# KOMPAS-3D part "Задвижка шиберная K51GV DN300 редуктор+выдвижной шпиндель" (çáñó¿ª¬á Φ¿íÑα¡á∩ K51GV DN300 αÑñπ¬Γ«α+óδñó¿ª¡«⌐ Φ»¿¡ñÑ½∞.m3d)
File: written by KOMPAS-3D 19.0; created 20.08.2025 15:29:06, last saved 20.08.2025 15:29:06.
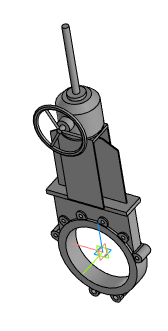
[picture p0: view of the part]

Document properties: Полное имя файла: Задвижка шиберная K51GV DN300 редуктор+выдвижной шпиндель.a3d

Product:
- Part/product: Задвижка шиберная K51GV DN300 редуктор+выдвижной шпиндель
    Масса: 97.9155

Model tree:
1. Операция без истории:1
